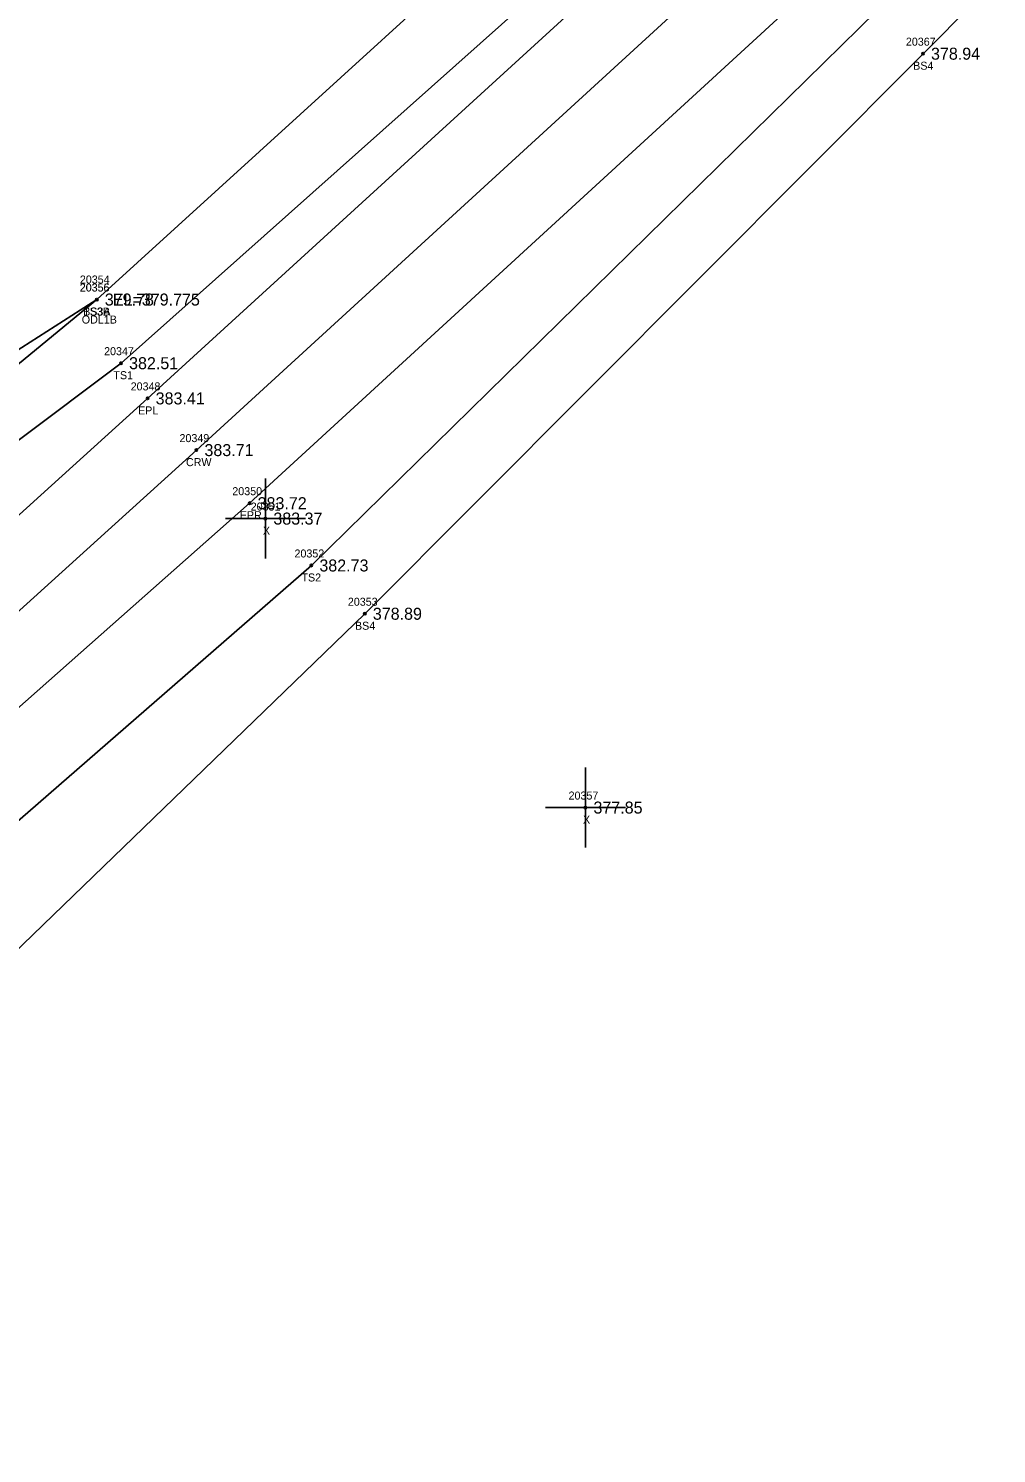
# Model space of a CAD drawing. Extents: x 2116373 to 2118139, y 979529 to 981026.
# Drawn here: x 2117528.6 to 2117649.6, y 980201.2 to 980379.2 of the extents above; entities that cross this region are included whole.
import ezdxf

# ---------------------------------------------------------------- set-up
doc = ezdxf.new("R2010")
doc.units = 0
for name, color, linetype in [('RD_DTM_BkLn1', 7, 'Continuous'), ('RD_DTM_BkLn2', 7, 'Continuous'), ('RD_DTM_BkLn_txCode', 7, 'Continuous'), ('RD_EX_H2O', 7, 'Continuous'), ('RD_EX_H2O_txCode', 7, 'Continuous'), ('RD_EX_Misc', 7, 'Continuous'), ('RD_EX_Misc_txCode', 7, 'Continuous'), ('RD_EX_Road', 7, 'Continuous'), ('RD_EX_Road_txCode', 7, 'Continuous'), ('RD_EX_TX_H2O_ELEV', 7, 'Continuous'), ('RD_EX_TX_Misc_ELEV', 7, 'Continuous'), ('RD_EX_TX_Road_ELEV', 7, 'Continuous'), ('RD_HC_Survey_ELEV', 7, 'Continuous'), ('RD_HC_Survey_txCode', 7, 'Continuous'), ('RD_SMD_Locator', 7, 'Continuous')]:
    doc.layers.add(name, color=color, linetype=linetype)

msp = doc.modelspace()

# ---------------------------------------------------------------- linework, layer by layer
at = {"layer": 'RD_DTM_BkLn1'}
msp.add_lwpolyline([(2117394.63, 980185.41), (2117475.35, 980259.39), (2117549.63, 980326.58), (2117623.5, 980394.2), (2117697.55, 980461.75), (2117735.02, 980495.39), (2117805.43, 980566.78), (2117837.53, 980605.36), (2117867.93, 980645.06), (2117897.09, 980686.34), (2117923.66, 980727.51), (2117948.72, 980771.39), (2117971.22, 980818.34), (2117988.96, 980866.05), (2117991.42, 980873.14), (2118004.26, 980915.09), (2118016.82, 980963.49), (2118028.02, 981013.26)], dxfattribs=at)
at = {"layer": 'RD_DTM_BkLn2'}
msp.add_line((2117493.39, 980317.39), (2117537.18, 980345.39), dxfattribs=at)
for points in [[(2117493.39, 980317.39), (2117496.3, 980311.64), (2117501.39, 980308.35), (2117540.21, 980337.44), (2117614.76, 980403.8), (2117689.51, 980469.61), (2117729.91, 980504.53), (2117761.86, 980538.86), (2117795.32, 980575.41), (2117828.25, 980612.61), (2117859.59, 980651.69), (2117887.1, 980692.35), (2117913.78, 980733.2), (2117937.24, 980777.08), (2117959.23, 980820.82), (2117978.84, 980869.89), (2117994.26, 980920.18), (2118007.51, 980964.57), (2118017.18, 981016.23)], [(2117403.18, 980177.15), (2117405.35, 980174.66), (2117487.26, 980245.43), (2117563.99, 980312.17), (2117634.65, 980381.46), (2117704.3, 980451.46), (2117722.65, 980465.11), (2117743.87, 980484.9), (2117780.03, 980521.07), (2117815.83, 980557.8), (2117846.79, 980597.78), (2117878.62, 980636.27), (2117911.26, 980677.34), (2117934.7, 980720.41), (2117959.82, 980759.29), (2117971.51, 980778.31), (2117986.8, 980774.26), (2117987.85, 980770.9), (2117995.22, 980745.17), (2118001.26, 980694.98), (2118008.4, 980640.04)], [(2117537.18, 980345.39), (2117608.78, 980410.55), (2117660.7, 980455.28)], [(2117389.45, 980162.29), (2117496.47, 980234.47), (2117570.67, 980306.14), (2117640.42, 980376.1), (2117709.81, 980445.93), (2117716.62, 980450.81)]]:
    msp.add_lwpolyline(points, dxfattribs=at)
at = {"layer": 'RD_EX_H2O'}
msp.add_line((2117498.72, 980313.84), (2117537.18, 980345.39), dxfattribs=at)
at = {"layer": 'RD_EX_Misc'}
for p, q in [((2117558.24, 980313.03), (2117558.24, 980323.03)), ((2117553.24, 980318.03), (2117563.24, 980318.03)), ((2117598.24, 980276.93), (2117598.24, 980286.93)), ((2117593.24, 980281.93), (2117603.24, 980281.93))]:
    msp.add_line(p, q, dxfattribs=at)
at = {"layer": 'RD_EX_Road'}
for points in [[(2117394.63, 980185.41), (2117388.45, 980192.75), (2117469.76, 980266.25), (2117487.02, 980282.1), (2117515.02, 980307.24), (2117543.53, 980333.04), (2117617.72, 980400.8), (2117691.88, 980468.07), (2117729.57, 980501.96), (2117798.93, 980572.83), (2117831.02, 980611), (2117861.69, 980650.07), (2117890.37, 980690.61), (2117916.67, 980731.93), (2117941.38, 980774.84), (2117963.75, 980821.95), (2117981.56, 980869.78), (2117996.2, 980917.73), (2118008.9, 980966.42), (2118019.55, 981015.46)], [(2117394.63, 980185.41), (2117401.85, 980177.36), (2117480.62, 980253.04), (2117556.27, 980319.95), (2117629.74, 980387.35), (2117703.2, 980454.29), (2117741.39, 980488.9), (2117777.53, 980523.58), (2117812.39, 980561.12), (2117844.66, 980599.64), (2117874.87, 980639.35), (2117904.78, 980681.4), (2117931.2, 980722.71), (2117957.05, 980767.35), (2117963.67, 980781.11), (2117980.28, 980814.62), (2117994.42, 980851.98)]]:
    msp.add_lwpolyline(points, dxfattribs=at)
at = {"layer": 'RD_SMD_Locator'}
for centre in [(2117640.42, 980376.1), (2117537.18, 980345.39), (2117537.18, 980345.39), (2117537.18, 980345.39), (2117540.21, 980337.44), (2117543.53, 980333.04), (2117549.63, 980326.58), (2117556.27, 980319.95), (2117558.24, 980318.03), (2117563.99, 980312.17), (2117570.67, 980306.14), (2117598.24, 980281.93)]:
    msp.add_circle(centre, 0.15, dxfattribs=at)

# ---------------------------------------------------------------- texts
at = {"layer": 'RD_DTM_BkLn_txCode'}
for s, p in [('20367', (2117638.28, 980377.1)), ('BS4', (2117639.19, 980374.1)), ('20356', (2117535.04, 980346.39)), ('20355', (2117535.06, 980346.39)), ('TS3B', (2117535.47, 980343.39)), ('BS3A', (2117535.47, 980343.39)), ('20347', (2117538.09, 980338.44)), ('TS1', (2117539.25, 980335.44)), ('20352', (2117561.88, 980313.17)), ('TS2', (2117562.75, 980310.17)), ('20353', (2117568.55, 980307.14)), ('BS4', (2117569.44, 980304.14))]:
    msp.add_text(s, height=1, dxfattribs=at).set_placement(p)
at = {"layer": 'RD_EX_H2O_txCode'}
for s, p in [('20354', (2117535.06, 980347.39)), ('ODL1B', (2117535.3, 980342.39))]:
    msp.add_text(s, height=1, dxfattribs=at).set_placement(p)
at = {"layer": 'RD_EX_Misc_txCode'}
for s, p in [('20351', (2117556.41, 980319.03)), ('X', (2117557.93, 980316.03)), ('20357', (2117596.13, 980282.93)), ('X', (2117597.93, 980279.93))]:
    msp.add_text(s, height=1, dxfattribs=at).set_placement(p)
at = {"layer": 'RD_EX_Road_txCode'}
for s, p in [('20348', (2117541.41, 980334.04)), ('EPL', (2117542.33, 980331.04)), ('20350', (2117554.11, 980320.95)), ('EPR', (2117555.04, 980317.95))]:
    msp.add_text(s, height=1, dxfattribs=at).set_placement(p)
at = {"layer": 'RD_EX_TX_H2O_ELEV'}
msp.add_text('EL=379.775', height=1.5, dxfattribs=at).set_placement((2117539.18, 980344.64))
at = {"layer": 'RD_EX_TX_Misc_ELEV'}
for s, p in [('378.94', (2117641.42, 980375.35)), ('379.78', (2117538.18, 980344.64)), ('379.78', (2117538.18, 980344.64)), ('382.51', (2117541.21, 980336.69)), ('383.37', (2117559.24, 980317.28)), ('382.73', (2117564.99, 980311.42)), ('378.89', (2117571.67, 980305.39)), ('377.85', (2117599.24, 980281.18))]:
    msp.add_text(s, height=1.5, dxfattribs=at).set_placement(p)
at = {"layer": 'RD_EX_TX_Road_ELEV'}
for s, p in [('383.41', (2117544.53, 980332.29)), ('383.72', (2117557.27, 980319.2))]:
    msp.add_text(s, height=1.5, dxfattribs=at).set_placement(p)
at = {"layer": 'RD_HC_Survey_ELEV'}
msp.add_text('383.71', height=1.5, dxfattribs=at).set_placement((2117550.63, 980325.83))
at = {"layer": 'RD_HC_Survey_txCode'}
for s, p in [('20349', (2117547.51, 980327.58)), ('CRW', (2117548.32, 980324.58))]:
    msp.add_text(s, height=1, dxfattribs=at).set_placement(p)

doc.saveas('drawing.dxf')
